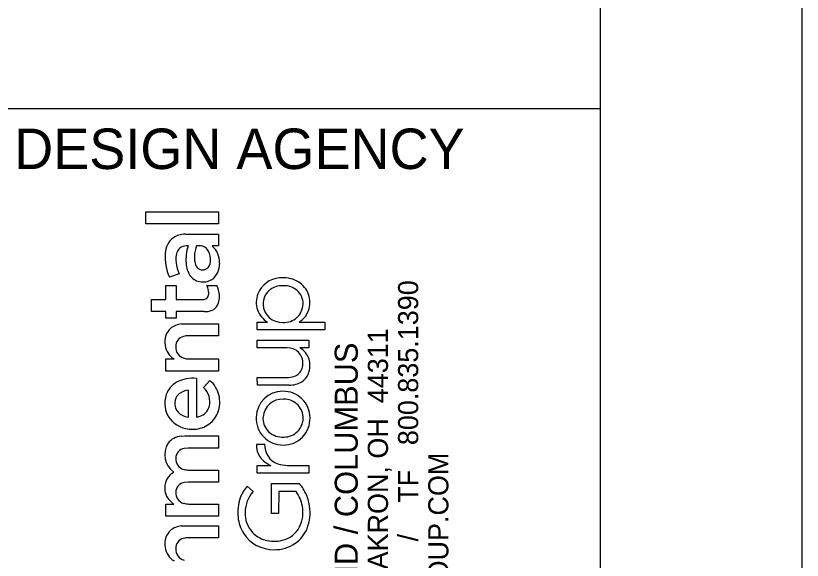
# Model space of a CAD drawing. Extents: x 0 to 34, y 0 to 22.
# Drawn here: x 32.054 to 34, y 3.382 to 4.729 of the extents above; entities that cross this region are included whole.
import ezdxf

# ---------------------------------------------------------------- set-up
doc = ezdxf.new("R2010")
doc.units = 0
for name, color, linetype in [('SH_Border', 7, 'Continuous'), ('SH_Cut_Line', 7, 'Continuous'), ('SH_Data', 7, 'Continuous'), ('SH_Text', 7, 'Continuous')]:
    doc.layers.add(name, color=color, linetype=linetype)

msp = doc.modelspace()

# ---------------------------------------------------------------- linework, layer by layer
at = {"layer": 'SH_Border'}
msp.add_line((32, 4.5), (33.5, 4.5), dxfattribs=at)
msp.add_lwpolyline([(1.5, 21.5), (33.5, 21.5), (33.5, 0.5), (1.5, 0.5)], close=True, dxfattribs=at)
at = {"layer": 'SH_Cut_Line'}
msp.add_lwpolyline([(0, 0), (34, 0), (34, 22), (0, 22)], close=True, dxfattribs=at)
at = {"layer": 'SH_Data'}
msp.add_line((32.75, 3.5), (32.75, 3.5), dxfattribs=at)
at = {"layer": 'SH_Text'}
for p, q in [((32.3756, 4.2141), (32.3756, 4.244)), ((32.3756, 4.244), (32.5557, 4.244)), ((32.5557, 4.244), (32.5557, 4.2141)), ((32.5557, 4.2141), (32.3756, 4.2141)), ((32.4727, 4.189), (32.5555, 4.1892)), ((32.5555, 4.1892), (32.5557, 4.1596)), ((32.5557, 4.1596), (32.5397, 4.1596)), ((32.4582, 4.0904), (32.4343, 4.0823)), ((32.4254, 4.027), (32.4255, 4.0621)), ((32.4255, 4.0621), (32.4511, 4.0621)), ((32.4511, 4.0621), (32.4512, 4.027)), ((32.527, 4.0616), (32.5511, 4.0616)), ((32.3896, 3.9972), (32.3896, 4.027)), ((32.3896, 4.027), (32.4254, 4.027)), ((32.4512, 4.027), (32.515, 4.027)), ((32.515, 4.027), (32.52, 4.0275)), ((32.4254, 3.9972), (32.3896, 3.9972)), ((32.4254, 3.9807), (32.4254, 3.9972)), ((32.5197, 3.9972), (32.4511, 3.9972)), ((32.4511, 3.9972), (32.4511, 3.9807)), ((32.4511, 3.9807), (32.4254, 3.9807)), ((32.6515, 3.9521), (32.6515, 3.9711)), ((32.6515, 3.9711), (32.6771, 3.9711)), ((32.7549, 3.9713), (32.8186, 3.9711)), ((32.8186, 3.9711), (32.8184, 3.9521)), ((32.4644, 3.9669), (32.4729, 3.9673)), ((32.4729, 3.9673), (32.5557, 3.9673)), ((32.5557, 3.9673), (32.5557, 3.9375)), ((32.8184, 3.9521), (32.6515, 3.9521)), ((32.5557, 3.9375), (32.4814, 3.9375)), ((32.6515, 3.908), (32.6515, 3.9267)), ((32.6515, 3.9267), (32.7791, 3.9266)), ((32.7791, 3.9266), (32.7791, 3.908)), ((32.7249, 3.908), (32.6515, 3.908)), ((32.7328, 3.9073), (32.7249, 3.908)), ((32.7791, 3.908), (32.7569, 3.908)), ((32.4254, 3.8503), (32.4254, 3.8802)), ((32.4254, 3.8802), (32.4455, 3.8802)), ((32.4822, 3.8802), (32.5557, 3.8802)), ((32.5557, 3.8802), (32.5557, 3.8504)), ((32.5557, 3.8504), (32.4254, 3.8503)), ((32.6515, 3.8344), (32.7291, 3.8345)), ((32.6517, 3.8154), (32.6515, 3.8344)), ((32.5011, 3.8321), (32.5012, 3.7366)), ((32.5188, 3.8093), (32.5342, 3.8266)), ((32.7307, 3.8154), (32.6517, 3.8154)), ((32.4814, 3.7364), (32.4814, 3.803)), ((32.4802, 3.7363), (32.4814, 3.7364)), ((32.4633, 3.6891), (32.4726, 3.6897)), ((32.4726, 3.6897), (32.5556, 3.6897)), ((32.5556, 3.6897), (32.5557, 3.6598)), ((32.4806, 3.6598), (32.471, 3.6588)), ((32.5557, 3.6598), (32.4806, 3.6598)), ((32.6493, 3.6691), (32.6698, 3.6691)), ((32.4444, 3.5992), (32.4446, 3.6007)), ((32.4822, 3.6055), (32.5557, 3.6055)), ((32.5557, 3.6055), (32.5557, 3.5757)), ((32.6515, 3.598), (32.6515, 3.617)), ((32.6515, 3.617), (32.6848, 3.617)), ((32.726, 3.617), (32.7791, 3.617)), ((32.7791, 3.617), (32.779, 3.598)), ((32.779, 3.598), (32.6515, 3.598)), ((32.4809, 3.5757), (32.4714, 3.5747)), ((32.5557, 3.5757), (32.4809, 3.5757)), ((32.6264, 3.5655), (32.6411, 3.5524)), ((32.6868, 3.5718), (32.7552, 3.5719)), ((32.6868, 3.4978), (32.6868, 3.5718)), ((32.7045, 3.5524), (32.7043, 3.4978)), ((32.7474, 3.5523), (32.7045, 3.5524)), ((32.4254, 3.4915), (32.4254, 3.5214)), ((32.4254, 3.5214), (32.4451, 3.5214)), ((32.4821, 3.5214), (32.5557, 3.5214)), ((32.5557, 3.5214), (32.5557, 3.4916)), ((32.5557, 3.4916), (32.4254, 3.4915)), ((32.7043, 3.4978), (32.6868, 3.4978)), ((32.4644, 3.4674), (32.4729, 3.4678)), ((32.4729, 3.4678), (32.5557, 3.4678)), ((32.5557, 3.4678), (32.5557, 3.438)), ((32.5557, 3.438), (32.4814, 3.438))]:
    msp.add_line(p, q, dxfattribs=at)
msp.add_lwpolyline([(32.3756, 4.2141), (32.3756, 4.244), (32.5557, 4.244), (32.5557, 4.2141)], close=True, dxfattribs=at)
for points in [[(32.4727, 4.189), (32.5555, 4.1892), (32.5557, 4.1596)], [(32.5557, 4.1596), (32.5397, 4.1596)], [(32.4582, 4.0904), (32.4343, 4.0823)], [(32.5197, 3.9972), (32.4511, 3.9972), (32.4511, 3.9807), (32.4254, 3.9807), (32.4254, 3.9972), (32.3896, 3.9972), (32.3896, 4.027), (32.4254, 4.027), (32.4255, 4.0621), (32.4511, 4.0621), (32.4512, 4.027), (32.515, 4.027), (32.52, 4.0275)], [(32.527, 4.0616), (32.5511, 4.0616)], [(32.7549, 3.9713), (32.8186, 3.9711), (32.8184, 3.9521), (32.6515, 3.9521)], [(32.6515, 3.9521), (32.6515, 3.9711), (32.6771, 3.9711)], [(32.4644, 3.9669), (32.4729, 3.9673), (32.5557, 3.9673), (32.5557, 3.9375), (32.4814, 3.9375)], [(32.7328, 3.9073), (32.7249, 3.908), (32.6515, 3.908), (32.6515, 3.9267), (32.7791, 3.9266), (32.7791, 3.908), (32.7569, 3.908)], [(32.4254, 3.8503), (32.4254, 3.8802), (32.4455, 3.8802)], [(32.4822, 3.8802), (32.5557, 3.8802), (32.5557, 3.8504), (32.4254, 3.8503)], [(32.7307, 3.8154), (32.6517, 3.8154), (32.6515, 3.8344), (32.7291, 3.8345)], [(32.5011, 3.8321), (32.5012, 3.7366)], [(32.5188, 3.8093), (32.5342, 3.8266)], [(32.4802, 3.7363), (32.4814, 3.7364), (32.4814, 3.803)], [(32.4633, 3.6891), (32.4726, 3.6897), (32.5556, 3.6897), (32.5557, 3.6598), (32.4806, 3.6598), (32.471, 3.6588)], [(32.6493, 3.6691), (32.6698, 3.6691)], [(32.4444, 3.5992), (32.4446, 3.6007)], [(32.4822, 3.6055), (32.5557, 3.6055), (32.5557, 3.5757), (32.4809, 3.5757), (32.4714, 3.5747)], [(32.6515, 3.598), (32.6515, 3.617), (32.6848, 3.617)], [(32.726, 3.617), (32.7791, 3.617), (32.779, 3.598), (32.6515, 3.598)], [(32.6264, 3.5655), (32.6411, 3.5524)], [(32.7474, 3.5523), (32.7045, 3.5524), (32.7043, 3.4978), (32.6868, 3.4978), (32.6868, 3.5718), (32.7552, 3.5719)], [(32.4254, 3.4915), (32.4254, 3.5214), (32.4451, 3.5214)], [(32.4821, 3.5214), (32.5557, 3.5214), (32.5557, 3.4916), (32.4254, 3.4915)], [(32.4644, 3.4674), (32.4729, 3.4678), (32.5557, 3.4678), (32.5557, 3.438), (32.4814, 3.438)]]:
    msp.add_lwpolyline(points, dxfattribs=at)
for centre, radius, start, end in [((32.4745, 4.1326), 0.0565, 91.8942, 122.6317), ((32.4745, 4.1326), 0.0565, 91.8942, 122.6317), ((32.4685, 4.1447), 0.043, 124.537, 155.6594), ((32.4685, 4.1447), 0.043, 124.537, 155.6594), ((32.4882, 4.1361), 0.0646, 155.9764, 175.3149), ((32.4882, 4.1361), 0.0646, 155.9764, 175.3149), ((32.4753, 4.1356), 0.024, 119.4252, 161.6629), ((32.4753, 4.1356), 0.024, 119.4252, 161.6629), ((32.4779, 4.1278), 0.0321, 85.3802, 116.6222), ((32.4779, 4.1278), 0.0321, 85.3802, 116.6222), ((32.5879, 4.1251), 0.1129, 162.0821, 184.5285), ((32.5879, 4.1251), 0.1129, 162.0821, 184.5285), ((32.5801, 4.1313), 0.0841, 159.8366, 178.0362), ((32.5801, 4.1313), 0.0841, 159.8366, 178.0362), ((32.5051, 4.1074), 0.053, 79.6696, 94.2322), ((32.5051, 4.1074), 0.053, 79.6696, 94.2322), ((32.5089, 4.1364), 0.0238, 56.8913, 76.2149), ((32.5089, 4.1364), 0.0238, 56.8913, 76.2149), ((32.5052, 4.1318), 0.0297, 17.5984, 55.7282), ((32.5052, 4.1318), 0.0297, 17.5984, 55.7282), ((32.5055, 4.1191), 0.0529, 358.0746, 49.762), ((32.5055, 4.1191), 0.0529, 358.0746, 49.762), ((32.5364, 4.1308), 0.113, 174.6101, 205.3899), ((32.5364, 4.1308), 0.113, 174.6101, 205.3899), ((32.5076, 4.1265), 0.0576, 163.1369, 188.1675), ((32.5076, 4.1265), 0.0576, 163.1369, 188.1675), ((32.5466, 4.1303), 0.0506, 175.5903, 199.8857), ((32.5466, 4.1303), 0.0506, 175.5903, 199.8857), ((32.4916, 4.1264), 0.0443, 345.9408, 18.9919), ((32.4916, 4.1264), 0.0443, 345.9408, 18.9919), ((32.5473, 4.1297), 0.0973, 186.7598, 203.7981), ((32.5473, 4.1297), 0.0973, 186.7598, 203.7981), ((32.5328, 4.1187), 0.0575, 182.5676, 213.7144), ((32.5328, 4.1187), 0.0575, 182.5676, 213.7144), ((32.5164, 4.1189), 0.0184, 198.2844, 293.3081), ((32.5164, 4.1189), 0.0184, 198.2844, 293.3081), ((32.5152, 4.1199), 0.0199, 295.2883, 347.4639), ((32.5152, 4.1199), 0.0199, 295.2883, 347.4639), ((32.5019, 4.1168), 0.0566, 336.016, 0.5951), ((32.5019, 4.1168), 0.0566, 336.016, 0.5951), ((32.5175, 4.1097), 0.0394, 303.4436, 336.18), ((32.5175, 4.1097), 0.0394, 303.4436, 336.18), ((32.5149, 4.1078), 0.0366, 215.0668, 259.8133), ((32.5149, 4.1078), 0.0366, 215.0668, 259.8133), ((32.5175, 4.1131), 0.0423, 257.5256, 300.882), ((32.5175, 4.1131), 0.0423, 257.5256, 300.882), ((32.7108, 4.0182), 0.0624, 93.9866, 158.3119), ((32.7108, 4.0182), 0.0624, 93.9866, 158.3119), ((32.7156, 4.0065), 0.0746, 62.6889, 97.0135), ((32.7156, 4.0065), 0.0746, 62.6889, 97.0135), ((32.7212, 4.0191), 0.0608, 25.0657, 61.9602), ((32.7212, 4.0191), 0.0608, 25.0657, 61.9602), ((32.4863, 4.042), 0.0452, 10.1545, 25.723), ((32.4863, 4.042), 0.0452, 10.1545, 25.723), ((32.4957, 4.0436), 0.0356, 351.914, 10.2059), ((32.4957, 4.0436), 0.0356, 351.914, 10.2059), ((32.503, 4.0351), 0.0549, 336.589, 28.8991), ((32.503, 4.0351), 0.0549, 336.589, 28.8991), ((32.7092, 4.0167), 0.0434, 132.3289, 182.0949), ((32.7092, 4.0167), 0.0434, 132.3289, 182.0949), ((32.7138, 4.0102), 0.0513, 87.8965, 131.1812), ((32.7138, 4.0102), 0.0513, 87.8965, 131.1812), ((32.7175, 4.0102), 0.0513, 49.9089, 92.0363), ((32.7175, 4.0102), 0.0513, 49.9089, 92.0363), ((32.7215, 4.0173), 0.0433, 358.0487, 47.9447), ((32.7215, 4.0173), 0.0433, 358.0487, 47.9447), ((32.5184, 4.04), 0.0126, 277.6142, 353.7918), ((32.5184, 4.04), 0.0126, 277.6142, 353.7918), ((32.707, 4.0202), 0.0581, 158.656, 198.171), ((32.707, 4.0202), 0.0581, 158.656, 198.171), ((32.7245, 4.02), 0.0574, 301.9776, 25.6418), ((32.7245, 4.02), 0.0574, 301.9776, 25.6418), ((32.5291, 4.0261), 0.0275, 292.6889, 332.0598), ((32.5291, 4.0261), 0.0275, 292.6889, 332.0598), ((32.7135, 4.0181), 0.0478, 183.5974, 271.7045), ((32.7135, 4.0181), 0.0478, 183.5974, 271.7045), ((32.7172, 4.018), 0.0477, 267.3149, 357.4019), ((32.7172, 4.018), 0.0477, 267.3149, 357.4019), ((32.5209, 4.0486), 0.0514, 268.6727, 291.5235), ((32.5209, 4.0486), 0.0514, 268.6727, 291.5235), ((32.7103, 4.0243), 0.0627, 200.8399, 238.0162), ((32.7103, 4.0243), 0.0627, 200.8399, 238.0162), ((32.4635, 3.9255), 0.0402, 132.2238, 161.6823), ((32.4635, 3.9255), 0.0402, 132.2238, 161.6823), ((32.4687, 3.9172), 0.0499, 94.9706, 130.2248), ((32.4687, 3.9172), 0.0499, 94.9706, 130.2248), ((32.4787, 3.9211), 0.056, 162.274, 187.7917), ((32.4787, 3.9211), 0.056, 162.274, 187.7917), ((32.4748, 3.9116), 0.025, 103.6868, 182.214), ((32.4748, 3.9116), 0.025, 103.6868, 182.214), ((32.4811, 3.8915), 0.046, 89.6051, 105.3303), ((32.4811, 3.8915), 0.046, 89.6051, 105.3303), ((32.4703, 3.9209), 0.0476, 188.9646, 238.6987), ((32.4703, 3.9209), 0.0476, 188.9646, 238.6987), ((32.4774, 3.9085), 0.0276, 175.5844, 255.1382), ((32.4774, 3.9085), 0.0276, 175.5844, 255.1382), ((32.7271, 3.87), 0.0377, 33.5008, 81.3295), ((32.7271, 3.87), 0.0377, 33.5008, 81.3295), ((32.7324, 3.8648), 0.0496, 17.6221, 60.3897), ((32.7324, 3.8648), 0.0496, 17.6221, 60.3897), ((32.4818, 3.9224), 0.0421, 254.0891, 270.5284), ((32.4818, 3.9224), 0.0421, 254.0891, 270.5284), ((32.7241, 3.8695), 0.0405, 346.5618, 31.7539), ((32.7241, 3.8695), 0.0405, 346.5618, 31.7539), ((32.7234, 3.8641), 0.0584, 339.162, 15.6148), ((32.7234, 3.8641), 0.0584, 339.162, 15.6148), ((32.7337, 3.8662), 0.0304, 294.6321, 348.4863), ((32.7337, 3.8662), 0.0304, 294.6321, 348.4863), ((32.7275, 3.8808), 0.0463, 271.952, 294.0894), ((32.7275, 3.8808), 0.0463, 271.952, 294.0894), ((32.739, 3.859), 0.042, 303.1039, 338.1561), ((32.739, 3.859), 0.042, 303.1039, 338.1561), ((32.4789, 3.7737), 0.0558, 118.8294, 160.6224), ((32.4789, 3.7737), 0.0558, 118.8294, 160.6224), ((32.4918, 3.7487), 0.0839, 83.6212, 118.2845), ((32.4918, 3.7487), 0.0839, 83.6212, 118.2845), ((32.494, 3.7763), 0.0644, 13.5328, 51.3627), ((32.494, 3.7763), 0.0644, 13.5328, 51.3627), ((32.7321, 3.8726), 0.0571, 268.627, 301.4778), ((32.7321, 3.8726), 0.0571, 268.627, 301.4778), ((32.4844, 3.7607), 0.0424, 94.0131, 130.8806), ((32.4844, 3.7607), 0.0424, 94.0131, 130.8806), ((32.4803, 3.7702), 0.0549, 19.0387, 45.4432), ((32.4803, 3.7702), 0.0549, 19.0387, 45.4432), ((32.7143, 3.7348), 0.0655, 89.4821, 178.7775), ((32.7143, 3.7348), 0.0655, 89.4821, 178.7775), ((32.7158, 3.7341), 0.0662, 0.4227, 90.7613), ((32.7158, 3.7341), 0.0662, 0.4227, 90.7613), ((32.487, 3.7707), 0.0644, 160.5214, 215.7815), ((32.487, 3.7707), 0.0644, 160.5214, 215.7815), ((32.477, 3.7709), 0.0298, 132.9855, 177.1802), ((32.477, 3.7709), 0.0298, 132.9855, 177.1802), ((32.4872, 3.7743), 0.047, 344.6072, 17.0067), ((32.4872, 3.7743), 0.047, 344.6072, 17.0067), ((32.4829, 3.7738), 0.0758, 339.3543, 13.3771), ((32.4829, 3.7738), 0.0758, 339.3543, 13.3771), ((32.714, 3.7324), 0.0485, 87.6883, 175.017), ((32.714, 3.7324), 0.0485, 87.6883, 175.017), ((32.7166, 3.7304), 0.0505, 44.912, 90.7591), ((32.7166, 3.7304), 0.0505, 44.912, 90.7591), ((32.4782, 3.7697), 0.0311, 175.0014, 223.2876), ((32.4782, 3.7697), 0.0311, 175.0014, 223.2876), ((32.499, 3.7718), 0.035, 288.0108, 343.5536), ((32.499, 3.7718), 0.035, 288.0108, 343.5536), ((32.7196, 3.7345), 0.0455, 358.3228, 43.8349), ((32.7196, 3.7345), 0.0455, 358.3228, 43.8349), ((32.4855, 3.7783), 0.0423, 225.0645, 262.797), ((32.4855, 3.7783), 0.0423, 225.0645, 262.797), ((32.5013, 3.7568), 0.0202, 269.7004, 294.8729), ((32.5013, 3.7568), 0.0202, 269.7004, 294.8729), ((32.4955, 3.7698), 0.0626, 300.9439, 338.7322), ((32.4955, 3.7698), 0.0626, 300.9439, 338.7322), ((32.7108, 3.7331), 0.0453, 175.5147, 221.4205), ((32.7108, 3.7331), 0.0453, 175.5147, 221.4205), ((32.4891, 3.7752), 0.0687, 217.7434, 271.6561), ((32.4891, 3.7752), 0.0687, 217.7434, 271.6561), ((32.7148, 3.7334), 0.0661, 177.5373, 270.9452), ((32.7148, 3.7334), 0.0661, 177.5373, 270.9452), ((32.7167, 3.7327), 0.0654, 269.3083, 1.6791), ((32.7167, 3.7327), 0.0654, 269.3083, 1.6791), ((32.7193, 3.7337), 0.0457, 308.9038, 359.3095), ((32.7193, 3.7337), 0.0457, 308.9038, 359.3095), ((32.492, 3.777), 0.0706, 269.2053, 300.3357), ((32.492, 3.777), 0.0706, 269.2053, 300.3357), ((32.714, 3.7373), 0.0505, 222.6626, 268.3733), ((32.714, 3.7373), 0.0505, 222.6626, 268.3733), ((32.7157, 3.7386), 0.0518, 266.5531, 308.6725), ((32.7157, 3.7386), 0.0518, 266.5531, 308.6725), ((32.4664, 3.644), 0.0452, 93.9112, 142.3072), ((32.4664, 3.644), 0.0452, 93.9112, 142.3072), ((32.4759, 3.6437), 0.0532, 148.2879, 233.9556), ((32.4759, 3.6437), 0.0532, 148.2879, 233.9556), ((32.4738, 3.635), 0.024, 96.7576, 181.6251), ((32.4738, 3.635), 0.024, 96.7576, 181.6251), ((32.6988, 3.6666), 0.0495, 177.1621, 216.2802), ((32.6988, 3.6666), 0.0495, 177.1621, 216.2802), ((32.7173, 3.6664), 0.0476, 176.7699, 252.1504), ((32.7173, 3.6664), 0.0476, 176.7699, 252.1504), ((32.4758, 3.6324), 0.026, 175.8157, 256.1672), ((32.4758, 3.6324), 0.026, 175.8157, 256.1672), ((32.7098, 3.6755), 0.0637, 216.9153, 246.8862), ((32.7098, 3.6755), 0.0637, 216.9153, 246.8862), ((32.7269, 3.6917), 0.0747, 251.1388, 269.3469), ((32.7269, 3.6917), 0.0747, 251.1388, 269.3469), ((32.4817, 3.6505), 0.045, 254.3463, 270.6103), ((32.4817, 3.6505), 0.045, 254.3463, 270.6103), ((32.4714, 3.5612), 0.0488, 156.0638, 187.3493), ((32.4714, 3.5612), 0.0488, 156.0638, 187.3493), ((32.4619, 3.5645), 0.0387, 139.5245, 154.847), ((32.4619, 3.5645), 0.0387, 139.5245, 154.847), ((32.4638, 3.5627), 0.0414, 117.9163, 139.243), ((32.4638, 3.5627), 0.0414, 117.9163, 139.243), ((32.4742, 3.5506), 0.0243, 96.5532, 179.949), ((32.4742, 3.5506), 0.0243, 96.5532, 179.949), ((32.7016, 3.5019), 0.0986, 139.7948, 159.137), ((32.7016, 3.5019), 0.0986, 139.7948, 159.137), ((32.725, 3.5394), 0.0444, 30.9891, 47.161), ((32.725, 3.5394), 0.0444, 30.9891, 47.161), ((32.6709, 3.5002), 0.1111, 25.3031, 33.9618), ((32.6709, 3.5002), 0.1111, 25.3031, 33.9618), ((32.4646, 3.5597), 0.0418, 186.5579, 213.3885), ((32.4646, 3.5597), 0.0418, 186.5579, 213.3885), ((32.4761, 3.5486), 0.0263, 175.722, 255.7863), ((32.4761, 3.5486), 0.0263, 175.722, 255.7863), ((32.699, 3.5008), 0.0775, 138.258, 179.7006), ((32.699, 3.5008), 0.0775, 138.258, 179.7006), ((32.6789, 3.501), 0.0856, 10.0751, 36.8319), ((32.6789, 3.501), 0.0856, 10.0751, 36.8319), ((32.6704, 3.4999), 0.1117, 8.8034, 25.3348), ((32.6704, 3.4999), 0.1117, 8.8034, 25.3348), ((32.4789, 3.5708), 0.0598, 214.7043, 235.6872), ((32.4789, 3.5708), 0.0598, 214.7043, 235.6872), ((32.4819, 3.5652), 0.0438, 253.6672, 270.1498), ((32.4819, 3.5652), 0.0438, 253.6672, 270.1498), ((32.7187, 3.4997), 0.1154, 161.1438, 185.6281), ((32.7187, 3.4997), 0.1154, 161.1438, 185.6281), ((32.6842, 3.5006), 0.0804, 333.4669, 11.0367), ((32.6842, 3.5006), 0.0804, 333.4669, 11.0367), ((32.6756, 3.4998), 0.1065, 338.2887, 9.2855), ((32.6756, 3.4998), 0.1065, 338.2887, 9.2855), ((32.6934, 3.497), 0.0899, 185.5077, 212.0129), ((32.6934, 3.497), 0.0899, 185.5077, 212.0129), ((32.6881, 3.4973), 0.0668, 176.6658, 223.6912), ((32.6881, 3.4973), 0.0668, 176.6658, 223.6912), ((32.4687, 3.4177), 0.0499, 94.9706, 130.2248), ((32.4687, 3.4177), 0.0499, 94.9706, 130.2248), ((32.6987, 3.4955), 0.0652, 282.8815, 331.8147), ((32.6987, 3.4955), 0.0652, 282.8815, 331.8147), ((32.4635, 3.426), 0.0402, 132.2238, 161.6823), ((32.4635, 3.426), 0.0402, 132.2238, 161.6823), ((32.6921, 3.4975), 0.0891, 212.7022, 270.714), ((32.6921, 3.4975), 0.0891, 212.7022, 270.714), ((32.6905, 3.5001), 0.0704, 224.0215, 253.88), ((32.6905, 3.5001), 0.0704, 224.0215, 253.88), ((32.6984, 3.4917), 0.0824, 305.0306, 337.6757), ((32.6984, 3.4917), 0.0824, 305.0306, 337.6757), ((32.4787, 3.4216), 0.056, 162.274, 187.7917), ((32.4787, 3.4216), 0.056, 162.274, 187.7917), ((32.4748, 3.4121), 0.025, 103.6868, 182.214), ((32.4748, 3.4121), 0.025, 103.6868, 182.214), ((32.4811, 3.392), 0.046, 89.6051, 105.3303), ((32.4811, 3.392), 0.046, 89.6051, 105.3303), ((32.6932, 3.5125), 0.0831, 254.4535, 283.9512), ((32.6932, 3.5125), 0.0831, 254.4535, 283.9512), ((32.4703, 3.4214), 0.0476, 188.9646, 238.6987), ((32.4703, 3.4214), 0.0476, 188.9646, 238.6987), ((32.4774, 3.409), 0.0276, 175.5844, 255.1382), ((32.4774, 3.409), 0.0276, 175.5844, 255.1382), ((32.6943, 3.4998), 0.0914, 269.3273, 304.1963), ((32.6943, 3.4998), 0.0914, 269.3273, 304.1963)]:
    msp.add_arc(centre, radius, start, end, dxfattribs=at)

# ---------------------------------------------------------------- texts
at = {"layer": 'SH_Data'}
msp.add_text('DESIGN AGENCY', height=0.1, dxfattribs=at).set_placement((32.05, 4.35))
at = {"layer": 'SH_Text'}
for s, height, p in [('800.835.1390', 0.049846, (33.0497, 3.6671)), ('450 GRANT ST., AKRON, OH  44311', 0.049846, (32.9749, 2.8374)), ('AKRON / CLEVELAND / COLUMBUS', 0.056969, (32.9001, 2.638)), ('ENVDESIGNGROUP.COM', 0.049846, (33.1244, 2.8374)), ('TF', 0.04985, (33.0497, 3.5246)), ('/  ', 0.04985, (33.0497, 3.4288))]:
    msp.add_text(s, height=height, rotation=90, dxfattribs=at).set_placement(p)

doc.saveas('drawing.dxf')
